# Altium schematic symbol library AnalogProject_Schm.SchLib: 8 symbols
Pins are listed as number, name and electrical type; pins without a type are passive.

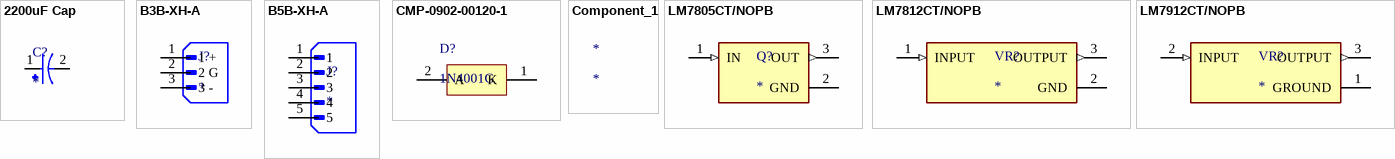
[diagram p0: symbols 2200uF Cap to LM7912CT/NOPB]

## 2200uF Cap
designator C?
2200 ÂµF 25 V Aluminum Electrolytic Capacitors Radial, Can - 5000 Hrs @ 105Â°C; MP: EEUFC1E222; MF: Panasonic
footprint 2200uF Cap
pins: 1 P, 2 N

## B3B-XH-A
designator J?, comment +
Connector Header Through Hole 3 position 0.098 (2.50mm); MF: JST Sales; MP: B3B-XH-A
footprint JST_B3B-XH-A
pins: 1 1 +, 2 2 G, 3 3 -

## B5B-XH-A
designator J?
Connector Header Through Hole 5 position 0.098 (2.50mm); MF: JST Sales; MP: B5B-XH-A
footprint JST_B5B-XH-A
pins: 1, 2, 3, 4, 5

## CMP-0902-00120-1
designator D?, comment 1N4001G
Diode, Rectifier, Standard, Vr 50V, If 1A, Pkg SOD57, Vf 0.93V, Tj +175C, Cs 30A, Ir 1UA; Manufacturer: On Semiconductor; Manufacturer Lifecycle Status: ACTIVE; Packing: Bulk Bag; IFSM Max (A): 30; Type: Standard Recovery; VRRM Max (V): 50; IO(rec) Max (A): 1; Element Configuration: Single; Forward Voltage: 1.1V; Peak Reverse Current: 10µA
footprint 1N4001_diode (AXIAL, 2-Leads, Diameter 2.35mm)
pins: 1 K, 2 A

## Component_1
designator *
Diode, Rectifier, Standard, Vr 50V, If 1A, Pkg SOD57, Vf 0.93V, Tj +175C, Cs 30A, Ir 1UA; Manufacturer: onsemi; Manufacturer Part Number: 1N4001G; Manufacturer Lifecycle Status: ACTIVE; Element Configuration: Single; Forward Voltage: 1.1V; Number of Elements: 1; Peak Reverse Current: 10µA

## LM7805CT/NOPB
designator Q?
Linear Voltage Regulator IC Positive Fixed 1 Output 1.5A TO-220-3; MF: ON Semiconductor; MP: LM7805CT
footprint LM7805
pins: 1 IN (in), 2 GND (power), 3 OUT (out)

## LM7812CT/NOPB
designator VR?
1.5-A, 30-V, linear voltage regulator; MF: Texas Instruments; MP: LM7812CT/NOPB
footprint LM7812
pins: 1 INPUT (in), 2 GND (power), 3 OUTPUT (out)

## LM7912CT/NOPB
designator VR?
1.5-A, negative linear voltage regulator; MF: Texas Instruments; MP: LM7912CT/NOPB
footprint LM7912
pins: 1 GROUND (power), 2 INPUT (in), 3 OUTPUT (out)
